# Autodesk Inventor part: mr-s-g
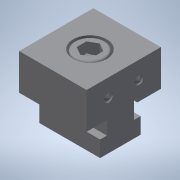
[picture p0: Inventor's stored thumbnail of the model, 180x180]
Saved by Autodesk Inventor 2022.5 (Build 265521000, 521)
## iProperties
Created: 2016-12
Part Number: mr-s-g
Material: 一般
Document SubType Name: Modeling
Designer: imaocorp
Density: 1 g/cm^3
Appearance: 既定
Author: imaocorp
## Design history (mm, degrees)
node "mr-s-g.x_t1"
node "mr-s-g"
node "Base1"
